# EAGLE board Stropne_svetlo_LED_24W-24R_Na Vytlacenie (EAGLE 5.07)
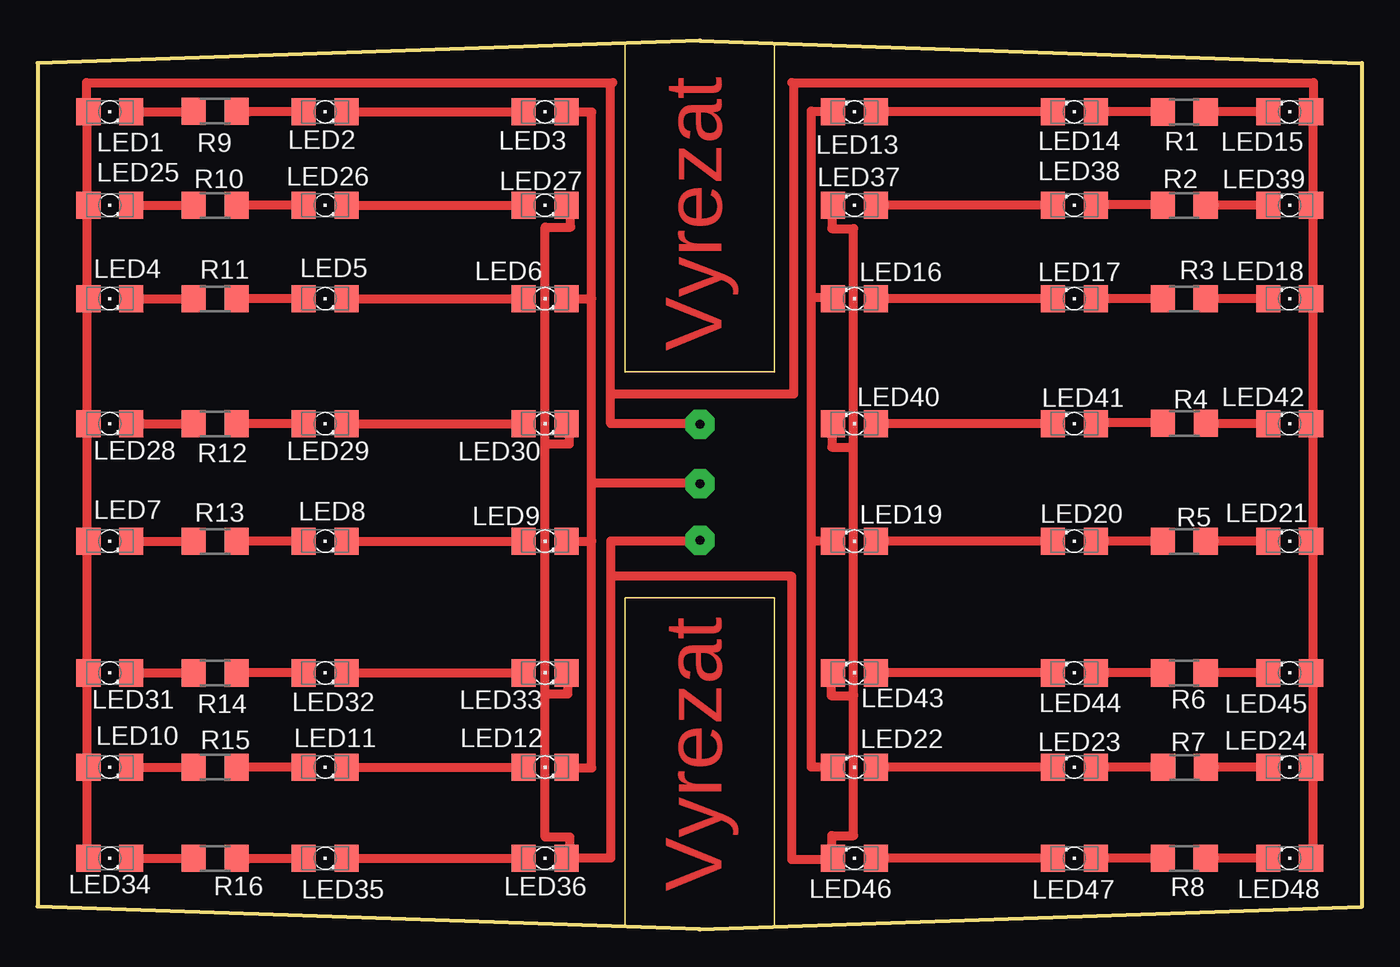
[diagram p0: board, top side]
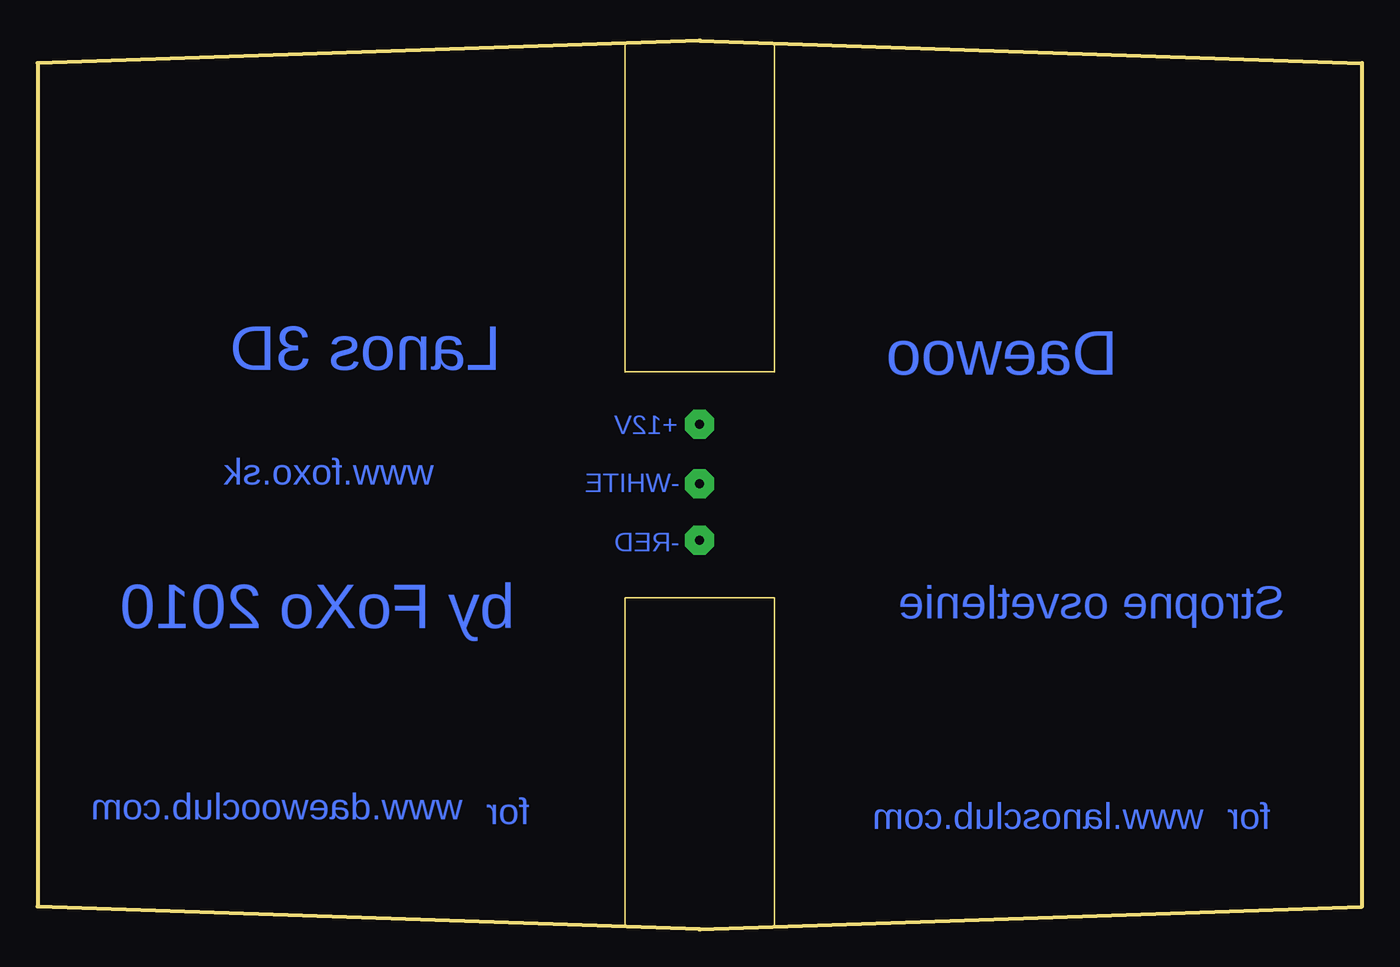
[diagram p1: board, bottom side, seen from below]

Size 87.95 x 59 mm. Coordinates in mm from the lower left corner, seen from the top.
Outline: 44,59 0,57.5 0,1.5 44,0
Outline: 39,58.75 39,37
Outline: 39,0.25 39,22
Outline: 44,37.02 39,37.02
Outline: 44,22.02 39,22.02
Outline: 43.95,59 87.95,57.5 87.95,1.5 43.95,0
Outline: 48.95,58.75 48.95,37
Outline: 48.95,0.25 48.95,22
Outline: 43.95,37.02 48.95,37.02
Outline: 43.95,22.02 48.95,22.02
Copper layers (1*16): Top 0.035mm / dielectric 1.5mm / Bottom 0.035mm
Design rules "default": minimum track width 10mil, minimum drill 24mil, track to track 8mil, track to pad 8mil, pad to pad 8mil, via to via 8mil, smd to smd 8mil, copper to edge 40mil, drill to drill 8mil, minimum pad ring 10mil, minimum via ring 8mil, stop-mask expansion 4mil, vias tented up to drill 0mil, thermal gap 10mil

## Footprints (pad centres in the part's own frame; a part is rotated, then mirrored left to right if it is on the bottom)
1206 = smd 1.6 x 1.803: A -1.422,0; C 1.422,0
R1206 = smd 1.6 x 1.803: 1 -1.422,0; 2 1.422,0

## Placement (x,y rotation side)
LED1  [1206]  4.8,54.27 0 top
LED2  [1206]  19.1,54.27 0 top
LED3  [1206]  33.7,54.27 0 top
LED4  [1206]  4.8,41.87 0 top
LED5  [1206]  19.1,41.87 0 top
LED6  [1206]  33.7,41.87 0 top
LED7  [1206]  4.8,25.77 0 top
LED8  [1206]  19.1,25.77 0 top
LED9  [1206]  33.7,25.77 0 top
LED10  [1206]  4.8,10.77 0 top
LED11  [1206]  19.1,10.77 0 top
LED12  [1206]  33.7,10.77 0 top
LED13  [1206]  54.25,54.27 180 top
LED14  [1206]  68.85,54.27 180 top
LED15  [1206]  83.15,54.27 180 top
LED16  [1206]  54.25,41.87 180 top
LED17  [1206]  68.85,41.87 180 top
LED18  [1206]  83.15,41.87 180 top
LED19  [1206]  54.25,25.77 180 top
LED20  [1206]  68.85,25.77 180 top
LED21  [1206]  83.15,25.77 180 top
LED22  [1206]  54.25,10.77 180 top
LED23  [1206]  68.85,10.77 180 top
LED24  [1206]  83.15,10.77 180 top
LED25  [1206]  4.8,48.07 0 top
LED26  [1206]  19.1,48.07 0 top
LED27  [1206]  33.7,48.07 0 top
LED28  [1206]  4.8,33.57 0 top
LED29  [1206]  19.1,33.57 0 top
LED30  [1206]  33.7,33.57 0 top
LED31  [1206]  4.8,17.02 0 top
LED32  [1206]  19.1,17.02 0 top
LED33  [1206]  33.7,17.02 0 top
LED34  [1206]  4.8,4.72 0 top
LED35  [1206]  19.1,4.72 0 top
LED36  [1206]  33.7,4.72 0 top
LED37  [1206]  54.25,48.07 180 top
LED38  [1206]  68.85,48.07 180 top
LED39  [1206]  83.15,48.07 180 top
LED40  [1206]  54.25,33.57 180 top
LED41  [1206]  68.85,33.57 180 top
LED42  [1206]  83.15,33.57 180 top
LED43  [1206]  54.25,17.02 180 top
LED44  [1206]  68.85,17.02 180 top
LED45  [1206]  83.15,17.02 180 top
LED46  [1206]  54.25,4.72 180 top
LED47  [1206]  68.85,4.72 180 top
LED48  [1206]  83.15,4.72 180 top
R1  [R1206]  76.14,54.26 0 top
R2  [R1206]  76.14,48.06 0 top
R3  [R1206]  76.14,41.86 0 top
R4  [R1206]  76.16,33.59 180 top
R5  [R1206]  76.14,25.76 0 top
R6  [R1206]  76.14,17.01 0 top
R7  [R1206]  76.17,10.75 180 top
R8  [R1206]  76.14,4.71 0 top
R9  [R1206]  11.79,54.31 0 top
R10  [R1206]  11.79,48.06 0 top
R11  [R1206]  11.79,41.86 0 top
R12  [R1206]  11.79,33.56 0 top
R13  [R1206]  11.79,25.76 0 top
R14  [R1206]  11.79,17.01 0 top
R15  [R1206]  11.79,10.76 0 top
R16  [R1206]  11.79,4.71 0 top

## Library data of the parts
LED1-LED48 = led
R1-R16 = resistor

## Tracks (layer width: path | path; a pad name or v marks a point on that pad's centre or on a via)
S$1
  Top 0.61: 6.95,54.27 9.7,54.27
S$2
  Top 0.61: 6.85,48.07 9.6,48.07
S$3
  Top 0.61: 6.9,41.87 9.65,41.87
S$4
  Top 0.61: 7,33.57 9.6,33.57
S$5
  Top 0.61: 6.85,25.77 9.7,25.77
S$6
  Top 0.61: 6.95,17.02 9.65,17.02
S$7
  Top 0.61: 6.85,10.77 9.65,10.77
S$8
  Top 0.61: 6.9,4.72 9.75,4.72
S$9
  Top 0.61: 21.2,4.72 31.6,4.72
S$10
  Top 0.61: 21.15,10.77 31.65,10.77
S$11
  Top 0.61: 21.2,17.02 31.6,17.02
S$12
  Top 0.61: 21.2,25.77 31.6,25.77
S$13
  Top 0.61: 21.2,33.57 31.6,33.57
S$14
  Top 0.61: 21.2,41.87 31.5,41.87
S$15
  Top 0.61: 21.2,48.07 31.55,48.07
S$16
  Top 0.61: 21.2,54.27 31.65,54.27
S$17
  Top 0.61: 3.25,53.62 3.25,5.12
S$18
  Top 0.61: 81,54.27 78.2,54.27
S$19
  Top 0.61: 81.1,48.07 78.05,48.07
S$20
  Top 0.61: 81.05,41.87 78.1,41.87
S$21
  Top 0.61: 80.95,33.57 78.15,33.57
S$22
  Top 0.61: 81.1,25.77 78.2,25.77
S$23
  Top 0.61: 81,17.02 78.2,17.02
S$24
  Top 0.61: 81.1,10.77 78.2,10.77
S$25
  Top 0.61: 81.05,4.72 78.25,4.72
S$26
  Top 0.61: 66.75,4.72 56.35,4.72
S$27
  Top 0.61: 66.8,10.77 56.3,10.77
S$28  (via drill 0.6 pad 1.93)
  other vias: 44,29.59
S$29
  Top 0.61: 66.75,17.02 56.35,17.02
S$30
  Top 0.61: 66.75,25.77 56.35,25.77
S$31
  Top 0.61: 66.75,33.57 56.35,33.57
S$32
  Top 0.61: 66.75,41.87 56.45,41.87
S$33
  Top 0.61: 66.75,48.07 56.4,48.07
S$34
  Top 0.61: 66.75,54.27 56.3,54.27
S$35
  Top 0.61: 84.7,53.62 84.7,5.12
S$36
  Top 0.61: 50.07,56.22 84.75,56.22
S$37
  Top 0.61: 84.75,54.67 84.75,56.22
S$38
  Top 0.61: 43.15,33.57 38.05,33.57 38.05,56.07
S$39
  Top 0.61: 52.3,41.92 51.38,41.92
S$40
  Top 0.61: 35.7,41.87 36.8,41.87
S$41
  Top 0.61: 35.7,25.77 36.8,25.77
S$42
  Top 0.61: 35.7,10.72 36.8,10.72 36.8,29.62 | 35.55,54.27 36.8,54.27 36.8,29.62 | 43.2,29.62 36.8,29.62
S$43
  Top 0.61: 52.35,25.77 51.53,25.77 | 52.2,10.77 51.38,10.77
S$44
  Top 0.61: 52.25,54.32 51.38,54.32 51.38,10.77
S$45
  Top 0.61: 43.25,25.77 38.05,25.77 38.05,4.72 35.65,4.72
S$46
  Top 0.61: 17.1,54.27 14.05,54.27 | 74,54.27 70.95,54.27 | 17.05,4.67 14,4.67 | 17,17.02 13.95,17.02 | 17,10.77 13.95,10.77 | 16.95,33.57 13.9,33.57 | 16.95,41.87 13.9,41.87 | 16.95,25.77 13.9,25.77 | 16.95,48.07 13.9,48.07 | 74.1,48.12 71.05,48.12 | 74.05,41.87 71,41.87 | 74,33.62 70.95,33.62 | 74,25.77 70.95,25.77 | 74.1,17.02 71.05,17.02 | 74,10.77 70.95,10.77 | 74.05,4.72 71,4.72
S$47
  Top 0.61: 35.3,32.87 35.3,32.22 33.81,32.22
S$48
  Top 0.406: 35.25,16.42 35.2,16.42
  Top 0.61: 35.2,16.42 35.2,15.62 33.71,15.62 | 35.35,5.47 35.35,6.12 33.71,6.12 33.71,15.62 | 35.4,47.37 35.4,46.62 33.71,46.62 33.71,15.62
S$49
  Top 0.61: 52.25,4.62 50.09,4.62 50.09,23.44 38.1,23.44
S$50  (via drill 0.6 pad 1.93)
  other vias: 44,33.54
S$51  (via drill 0.6 pad 1.93)
  other vias: 44,25.84
S$52
  Top 0.406: 54.19,15.52 54.19,15.57
  Top 0.61: 52.7,16.27 52.7,15.52 54.19,15.52 54.19,6.22 52.75,6.22 52.75,5.42 | 52.75,47.42 52.75,46.52 54.19,46.52 54.19,15.57
S$53
  Top 0.61: 52.75,32.72 52.75,32.02 54.14,32.02
S$54
  Top 0.61: 50.2,56.17 50.2,35.54 38.14,35.54
S$55
  Top 0.61: 38.19,56.22 3.25,56.22 3.25,54.92

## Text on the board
Top: Vyrezat | Vyrezat
Bottom: Daewoo | Lanos 3D | +12V | -WHITE | www.foxo.sk | -RED | Stropne osvetlenie | by FoXo 2010 | for | www.lanosclub.com | for | www.daewooclub.com
Text: Daewoo | Lanos | www.foxo.sk | www.lanosclub.com | Stropne | by FoXo 2010 | osvetlenie | for | 3 Dverova verzia | www.daewooclub.com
